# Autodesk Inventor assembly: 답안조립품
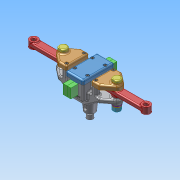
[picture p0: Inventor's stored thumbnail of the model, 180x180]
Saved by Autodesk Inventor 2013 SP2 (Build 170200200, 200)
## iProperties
Created: 2025-07
Part Number: 답안조립품
Document SubType Name: Assembly
Designer: a
Author: a
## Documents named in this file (11)
- C:\Users\a\Desktop\750703V1007\답안조립품.iam
- C:\Users\a\Desktop\750703V1007\본체.ipt
- C:\Users\a\Desktop\750703V1007\링크.ipt
- C:\Users\a\Desktop\750703V1007\슬라이더.ipt
- C:\Users\a\Desktop\750703V1007\링크 커버.ipt
- C:\Users\a\Desktop\750703V1007\슬라이더 커버.ipt
- C:\Users\a\Desktop\750703V1007\평 와셔 M8.ipt
- C:\Users\a\Desktop\750703V1007\스프링 와셔 M8.ipt
- C:\Users\a\Desktop\750703V1007\6각 너트 M8.ipt
- C:\Users\a\Desktop\750703V1007\핀.ipt
- C:\Users\a\Desktop\750703V1007\6각 구멍붙이 볼트 M3x10.ipt
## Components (12 placed, 3 different names)
1. 6각 너트 M8:1
2. 핀:1
3. 핀:2
4. 6각 너트 M8:2
5. 6각 구멍붙이 볼트 M3x10:1
6. 6각 구멍붙이 볼트 M3x10:2
7. 6각 구멍붙이 볼트 M3x10:3
8. 6각 구멍붙이 볼트 M3x10:4
9. 6각 구멍붙이 볼트 M3x10:5
10. 6각 구멍붙이 볼트 M3x10:6
11. 6각 구멍붙이 볼트 M3x10:7
12. 6각 구멍붙이 볼트 M3x10:8
